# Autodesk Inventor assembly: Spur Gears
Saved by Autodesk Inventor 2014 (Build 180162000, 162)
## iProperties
Created: 2010-12
Part Number: Spur Gears
Document SubType Name: Assembly
Designer: Thom Tremblay
Categories: <?xml version="1.0" encoding="UTF-16"?> <MemberInstance><Categories><FamilyTemplate/><ParamToTemplateMap><ParamToTemplate><ParamToTemplate CategoryParameter="//
ClientObjectVersion: 1
Author: Thom Tremblay
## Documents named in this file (1)
- C:\Inventor 2014 Essentials\Assemblies\Chapter 08\c08-01\Design Accelerator\Spur Gears4.iam
